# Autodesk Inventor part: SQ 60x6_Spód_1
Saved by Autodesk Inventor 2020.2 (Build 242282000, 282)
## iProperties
Created: 2006-08
Part Number: SQ 60x6_Spód_1
Material: Ogólny
Document SubType Name: Modeling
Designer: F.Stasiak
Manufacturer: Standard
Standards Organization: Custom
Stock Number: DIN EN 10210-2 SQ 60x6
Density: 1 g/cm^3
Appearance: Domyślna
Manager: www.cadconsulting.pl
Company: Fabian Stasiak CAD Consulting
G_L: 1500,0 mm
G_W: 60,000 mm
G_H: 60,000 mm
AFG_Item: 60 x 60 x 6
Author: F.Stasiak
Subject: Zbiór ćwiczeń. Autodesk Inventor 2020. Kurs podstawowy
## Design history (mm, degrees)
sketch "AFG_Detailed"
  geometry: L1 (-12, 54)-(-48, 54); L2 (-54, 48)-(-54, 12); L3 (-48, 6)-(-12, 6); L4 (-6, 12)-(-6, 48); L5 (-12, 60)-(-48, 60); L6 (-60, 48)-(-60, 12); L7 (-48, 0)-(-12, 0); L8 (0, 12)-(0, 48); A1 r 6 centre (-12, 48) between (-6, 48) and (-12, 54); A2 r 12 centre (-12, 48) between (0, 48) and (-12, 60); A3 r 6 centre (-12, 12) between (-12, 6) and (-6, 12); A4 r 12 centre (-12, 12) between (-12, 0) and (0, 12); A5 r 12 centre (-48, 12) between (-60, 12) and (-48, 0); A6 r 6 centre (-48, 12) between (-54, 12) and (-48, 6); A7 r 6 centre (-48, 48) between (-48, 54) and (-54, 48); A8 r 12 centre (-48, 48) between (-48, 60) and (-60, 48); 4 further points
  constraints: 16 end point, 16 point on circle, 16 tangent, 8 centre point, 6 point on line, 4 parallel, 2 perpendicular, 1 vertical
  dimensions: "d15" = 60 distance of point (-60, 0) point (0, 0) (= GEO_B); "d16" = 6 distance between parallel lines of L7 L3 (= GEO_S); "d17" = 6 distance between parallel lines of L8 L4 (= GEO_S); "d18" = 6 distance between parallel lines of L5 L1 (= GEO_S); "d19" = 6 distance between parallel lines of L6 L2 (= GEO_S); "d20" = 30 distance from line of point (-30, 30) L7 (= 0.5 x GEO_H); "d30" = 6 radius of A1 (= GEO_R1 - GEO_S); "GEO_R1" = 12 radius of A2; "d32" = 6 radius of A3 (= GEO_R1 - GEO_S); "d33" = 12 radius of A4 (= GEO_R1); "d34" = 12 radius of A5 (= GEO_R1); "d35" = 6 radius of A6 (= GEO_R1 - GEO_S); "d36" = 6 radius of A7 (= GEO_R1 - GEO_S); "d37" = 12 radius of A8 (= GEO_R1); "d38" = 30 distance from line of L6 point (-30, 30) (= 0.5 x GEO_B); "d39" = 60 distance between parallel lines of L7 L5 (= GEO_H)
sketch "AFG_Medium"
  geometry: L1 (-6, 54)-(-54, 54); L2 (-54, 54)-(-54, 6); L3 (-54, 6)-(-6, 6); L4 (-6, 6)-(-6, 54); L5 (0, 60)-(-60, 60); L6 (-60, 60)-(-60, 0); L7 (-60, 0)-(0, 0); L8 (0, 0)-(0, 60); 1 further point
  constraints: 16 end point, 4 parallel, 2 perpendicular, 1 vertical
  dimensions: "GEO_B" = 60 distance of L6.end L7.end; "GEO_S" = 6 distance between parallel lines of L7 L3; "d5" = 6 distance between parallel lines of L8 L4 (= GEO_S); "d6" = 6 distance between parallel lines of L5 L1 (= GEO_S); "d7" = 6 distance between parallel lines of L6 L2 (= GEO_S); "d12" = 30 distance from line of point (-30, 30) L7 (= 0.5 x GEO_H); "d40" = 60 distance between parallel lines of L7 L5 (= GEO_H); "d41" = 30 distance from line of L6 point (-30, 30) (= 0.5 x GEO_B)
sketch "AFG_Simplified"
  geometry: L1 (0, 60)-(-60, 60); L2 (-60, 60)-(-60, 0); L3 (-60, 0)-(0, 0); L4 (0, 0)-(0, 60); 1 further point
  constraints: 8 end point, 2 parallel, 1 perpendicular, 1 vertical
  dimensions: "d23" = 60 distance of L2.end L3.end (= GEO_B); "d28" = 30 distance from line of point (-30, 30) L3 (= 0.5 x GEO_H); "d42" = 60 distance between parallel lines of L3 L1 (= GEO_H); "d43" = 30 distance from line of point (-30, 30) L2 (= 0.5 x GEO_B)
derived "Szkielet podstawy.ipt"
  sketch "Szkic1"
    geometry: L1 (0, 0)-(1500, 0) reference; L2 (1500, 0)-(1500, 1000) reference; L3 (1500, 1000)-(0, 1000) reference; L4 (0, 1000)-(0, 0) reference
  sketch "Szkic2"
    geometry: L1 (0, 1000)-(0, 0) reference; L2 (0, 0)-(1500, 0) reference; L3 (1500, 0)-(1500, 1000) reference; L4 (500, 1000)-(1500, 1000) reference; L5 (1500, 1000)-(1500, 0) reference; L6 (1500, 0)-(500, 0) reference; L7 (500, 0)-(500, 1000) reference; L8 (1500, 1000)-(0, 1000) reference
node "AFG_StartWorkPoint_SQ 60x6_Spód_1"
node "AFG_EndWorkPoint_SQ 60x6_Spód_1"
node "AFG_HelpAxis"
node "AFG_HelpStart"
node "AFG_HelpEnd"
node "AFG_Midplane"
  node "AFG_Startplane"
  node "AFG_EndPlane"
node "AFG_Profile_AxisX_for_External_Matrix"
extrude "AFG_Detailed_SQ 60x6_Spód_1" join sketch "AFG_Detailed" stored distance "d49" = 0.13; taper "d50" = 0 deg
extrude "AFG_Simplified_SQ 60x6_Spód_1" join sketch "AFG_Simplified" stored distance "d51" = 0.13; taper "d52" = 0 deg
node "AFG_StartWorkPoint_SQ 60x6_Spód_2"
node "AFG_EndWorkPoint_SQ 60x6_Spód_2"
node "AFG_ENDCUTPLANE_SQ 60x6_Spód_1"
node "AFG_StartWorkPoint_SQ 60x6_Spód_4"
node "AFG_EndWorkPoint_SQ 60x6_Spód_4"
node "AFG_STARTCUTPLANE_SQ 60x6_Spód_1"
node "Bryła1"
node "Korpusy bryłowe"
node "Korpusy powierzchniowe"
other parameters: "GEO_H" = 60, "AFG_Origin_X" = 0 (= 0 x GEO_B) [user parameter], "AFG_Origin_Y" = 0 (= 0 x GEO_H) [user parameter], "AFG_IP_X2" = 0 (= 0 x GEO_B) [user parameter], "AFG_IP_Y4" = 0 (= 0 x GEO_H) [user parameter], "AFG_IP_X6" = 0 (= 0 x GEO_B) [user parameter], "AFG_IP_Y8" = 0 (= 0 x GEO_H) [user parameter], "d47" = 0, "d48" = 0, "G_L" = 1500 [user parameter], "d55" = 0, "d58" = 0
